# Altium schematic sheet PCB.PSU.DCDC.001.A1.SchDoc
size A3
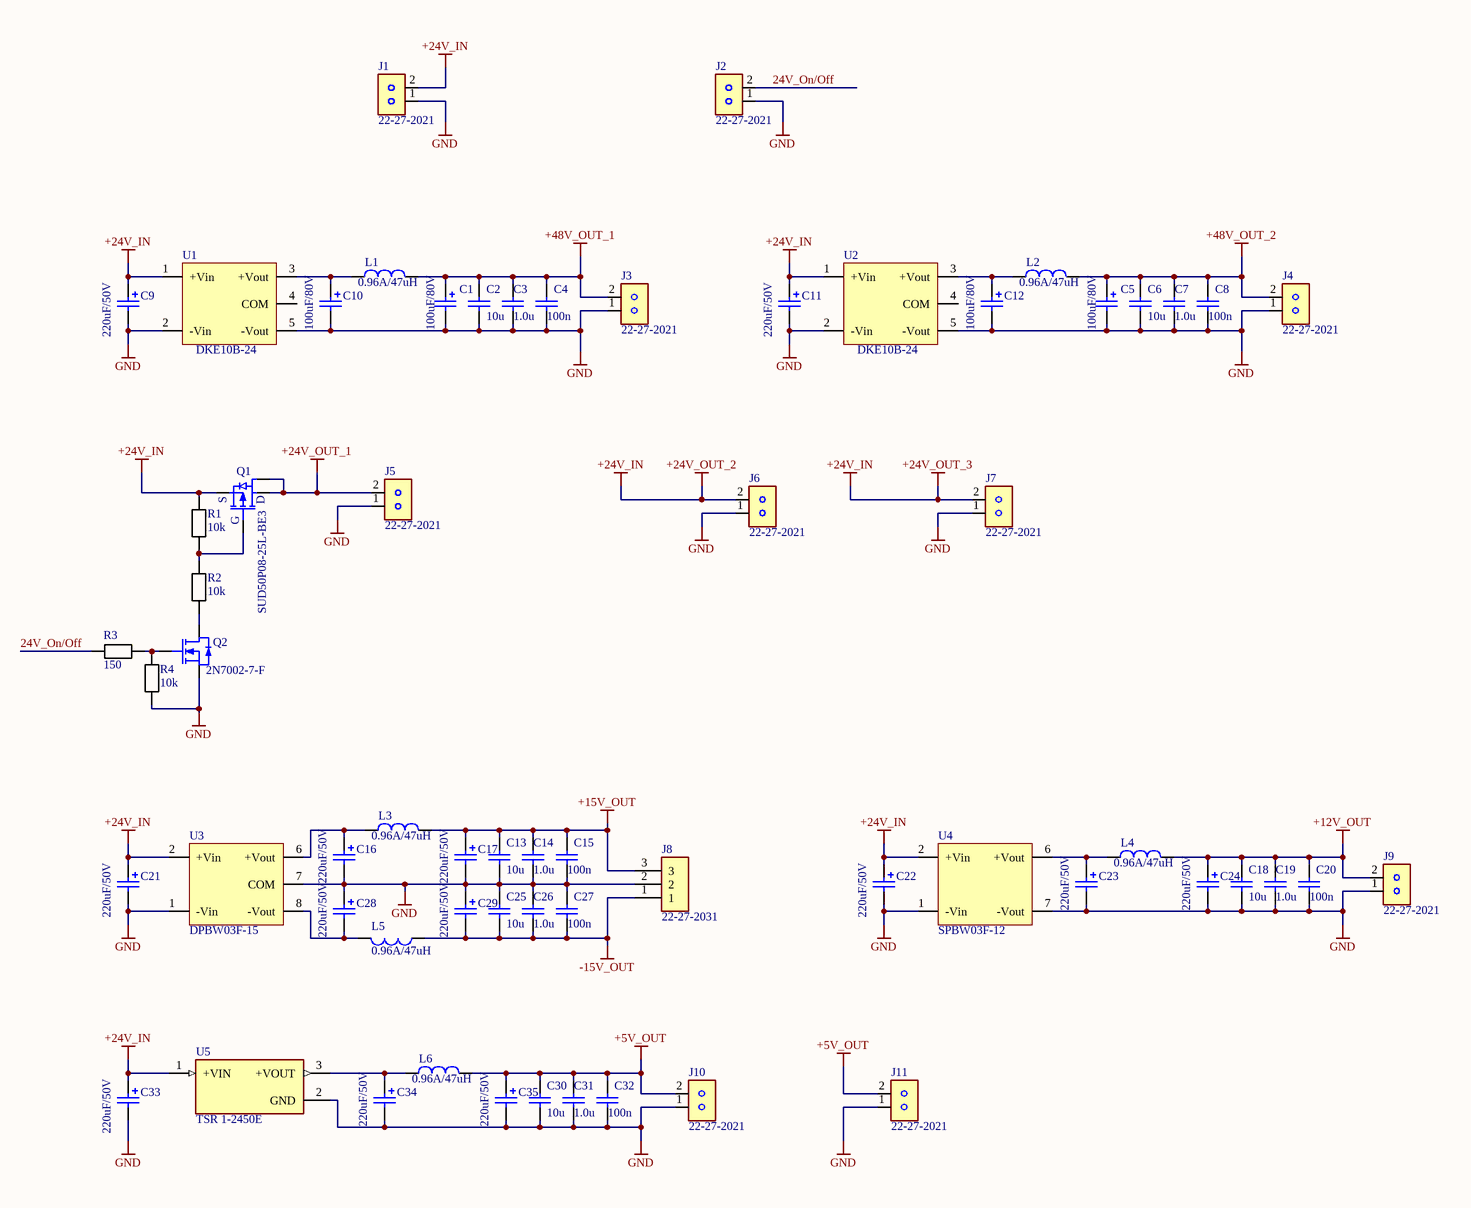
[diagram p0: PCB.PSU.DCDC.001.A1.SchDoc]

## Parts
C1  100uF/80V  [CAP_EEU-FS1K101B]
C2  10u  [C1206]
C3  1.0u  [C0603]
C4  100n  [C0603]
C5  100uF/80V  [CAP_EEU-FS1K101B]
C6  10u  [C1206]
C7  1.0u  [C0603]
C8  100n  [C0603]
C9  220uF/50V  [CAP_ESL227M050AH8AA]
C10  100uF/80V  [CAP_EEU-FS1K101B]
C11  220uF/50V  [CAP_ESL227M050AH8AA]
C12  100uF/80V  [CAP_EEU-FS1K101B]
C13  10u  [C1206]
C14  1.0u  [C0603]
C15  100n  [C0603]
C16  220uF/50V  [CAP_ESL227M050AH8AA]
C17  220uF/50V  [CAP_ESL227M050AH8AA]
C18  10u  [C1206]
C19  1.0u  [C0603]
C20  100n  [C0603]
C21  220uF/50V  [CAP_ESL227M050AH8AA]
C22  220uF/50V  [CAP_ESL227M050AH8AA]
C23  220uF/50V  [CAP_ESL227M050AH8AA]
C24  220uF/50V  [CAP_ESL227M050AH8AA]
C25  10u  [C1206]
C26  1.0u  [C0603]
C27  100n  [C0603]
C28  220uF/50V  [CAP_ESL227M050AH8AA]
C29  220uF/50V  [CAP_ESL227M050AH8AA]
C30  10u  [C1206]
C31  1.0u  [C0603]
C32  100n  [C0603]
C33  220uF/50V  [CAP_ESL227M050AH8AA]
C34  220uF/50V  [CAP_ESL227M050AH8AA]
C35  220uF/50V  [CAP_ESL227M050AH8AA]
J1  22-27-2021  [MOLEX_22-27-2021]
J2  22-27-2021  [MOLEX_22-27-2021]
J3  22-27-2021  [MOLEX_22-27-2021]
J4  22-27-2021  [MOLEX_22-27-2021]
J5  22-27-2021  [MOLEX_22-27-2021]
J6  22-27-2021  [MOLEX_22-27-2021]
J7  22-27-2021  [MOLEX_22-27-2021]
J8  22-27-2031  [MOLEX_22-27-2031]
J9  22-27-2021  [MOLEX_22-27-2021]
J10  22-27-2021  [MOLEX_22-27-2021]
J11  22-27-2021  [MOLEX_22-27-2021]
L1  0.96A/47uH  [IND_RLB0912]
L2  0.96A/47uH  [IND_RLB0912]
L3  0.96A/47uH  [IND_RLB0912]
L4  0.96A/47uH  [IND_RLB0912]
L5  0.96A/47uH  [IND_RLB0912]
L6  0.96A/47uH  [IND_RLB0912]
Q1  SUD50P08-25L-BE3  [TO-252-3]
Q2  2N7002-7-F  [SOT23-3N]
R1  10k  [R0603]
R2  10k  [R0603]
R3  150  [R0603]
R4  10k  [R0603]
U1  DKE10B-24  [DKE10B-24]
U2  DKE10B-24  [DKE10B-24]
U3  DPBW03F-15  [DPBW03F-15]
U4  SPBW03F-12  [SPBW03F-12]
U5  TSR 1-2450E  [CONV_TSR_1-2450E]

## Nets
+5V_OUT: C30.2 C31.2 C32.2 C35.1 J10.2 J11.2 L6.2
+12V_OUT: C18.2 C19.2 C20.2 C24.1 J9.2 L4.2
+15V_OUT: C13.2 C14.2 C15.2 C17.1 J8.3 L3.2
+24V_IN: C9.1 C11.1 C21.1 C22.1 C33.1 J1.2 J6.2 J7.2 Q1.3(S) R1.2 U1.1(+Vin) U2.1(+Vin) U3.2(+Vin) U4.2(+Vin) U5.1(+VIN)  [also labelled +24V_OUT_2, +24V_OUT_3]
+24V_OUT_1: J5.2 Q1.2(D)
+48V_OUT_1: C1.1 C2.2 C3.2 C4.2 J3.2 L1.2
+48V_OUT_2: C5.1 C6.2 C7.2 C8.2 J4.2 L2.2
-15V_OUT: C25.1 C26.1 C27.1 C29.2 J8.1 L5.1
GND: C1.2 C2.1 C3.1 C4.1 C5.2 C6.1 C7.1 C8.1 C9.2 C10.2 C11.2 C12.2 C13.1 C14.1 C15.1 C16.2 C17.2 C18.1 C19.1 C20.1 C21.2 C22.2 C23.2 C24.2 C25.2 C26.2 C27.2 C28.1 C29.1 C30.1 C31.1 C32.1 C33.2 C34.2 C35.2 J1.1 J2.1 J3.1 J4.1 J5.1 J6.1 J7.1 J8.2 J9.1 J10.1 J11.1 Q2.2(S) R4.1 U1.2(-Vin) U1.5(-Vout) U2.2(-Vin) U2.5(-Vout) U3.1(-Vin) U3.7(COM) U4.1(-Vin) U4.7(-Vout) U5.2(GND)
24V_On/Off: J2.2 R3.1
NetC10_1: C10.1 L1.1 U1.3(+Vout)
NetC12_1: C12.1 L2.1 U2.3(+Vout)
NetC16_1: C16.1 L3.1 U3.6(+Vout)
NetC23_1: C23.1 L4.1 U4.6(+Vout)
NetC28_2: C28.2 L5.2 U3.8(-Vout)
NetC34_1: C34.1 L6.1 U5.3(+VOUT)
NetQ1_1: Q1.1(G) R1.1 R2.2
NetQ2_1: Q2.1(G) R3.2 R4.2
NetQ2_3: Q2.3(D) R2.1

Not connected (* = marked no-connect by the designer): U1 4(COM); U2 4(COM)

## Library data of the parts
C1 C5 C10 C12 = Cap_Electrolytic: CAP ALUM 220UF 20% 50V SMD; MPN: EEU-FS1K101B; MFR: KEMET
C2 C6 C13 C18 C25 C30 = CAP_YAG_CC1206KKX7R8BB106: Capacitor 10u 1206 +-10% 25V; MFR: Yageo; Type: X7R; Voltage (V): 50
C3 C7 C14 C19 C26 C31 = CAP_YAG_CC0603KRX7R9BB105_X7R: Capacitor 1.0u 0603 +-10% 50V; MFR: Yageo; Type: X7R; Voltage (V): 50
C4 C8 C15 C20 C27 C32 = CAP_YAG_CC0603KRX7R9BB104_X7R: Capacitor 100n 0603 +-10% 50V; MFR: Yageo; Type: X7R; Voltage (V): 50
C9 C11 C16 C17 C21-C24 C28 C29 C33-C35 = Cap_Electrolytic: CAP ALUM 220UF 20% 50V SMD; MPN: ESL227M050AH8AA; MFR: KEMET
J1-J7 J9-J11 = 22-27-2021: Connector Wire to Board Header 2 Position 2.54mm Solder Straight Thru-Hole Ba; MFR: Molex
J8 = 22-27-2031: Connector Header Through Hole 3 position 0.100 _2.54mm_; MFR: Molex
L1-L6 = Inductor: Power Inductors - Leaded 47uH 10% .96A; MFR: Bourns; MPN: RLB0912-470KL
Q1 = SUD50P08-25L-BE3: MOSFET 80V P-CH MOSFET (D-S) 17; MFR: Vishay
Q2 = MOSFET-N: MOSFET N-CH 60V 200MA SOT23-3; MFR: Diodes Incorporated
R1 R2 R4 = RES_YAG_RC0603FR-0710KL: Resistor 10k 0603 +-1% 0.1; MFR: Yageo; Temperature Coefficient: +-200ppm°C; Power (Watts): 0.1; Voltage (V): 75
R3 = RES_YAG_RC0603FR-07150RL: Resistor 150 0603 +-1% 0.1; MFR: Yageo; Temperature Coefficient: +-200ppm°C; Power (Watts): 0.1; Voltage (V): 75
U1 U2 = DKE10B-24: Isolated DC/DC Converters - Through Hole 18-36Vin +/-24Vout 21-210mA, 10W; MFR: MEAN WELL
U3 = DPBW03F-15: Isolated DC/DC Converters - Through Hole 9-36Vin +/-15Vout +/-100mA SIP Reg Iso; MFR: MEAN WELL
U4 = SPBW03F-12: Isolated DC/DC Converters - Through Hole 9-36Vin 12Vout 250mA SIP8 Reg Iso; MFR: MEAN WELL
U5 = TSR_1-2450E: 1 Amp POL converter, industrial, 6-36 VDC input, pos.-pos. circuit, cost efficient, LM78 compatible, SIP-3; MFR: Traco Power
